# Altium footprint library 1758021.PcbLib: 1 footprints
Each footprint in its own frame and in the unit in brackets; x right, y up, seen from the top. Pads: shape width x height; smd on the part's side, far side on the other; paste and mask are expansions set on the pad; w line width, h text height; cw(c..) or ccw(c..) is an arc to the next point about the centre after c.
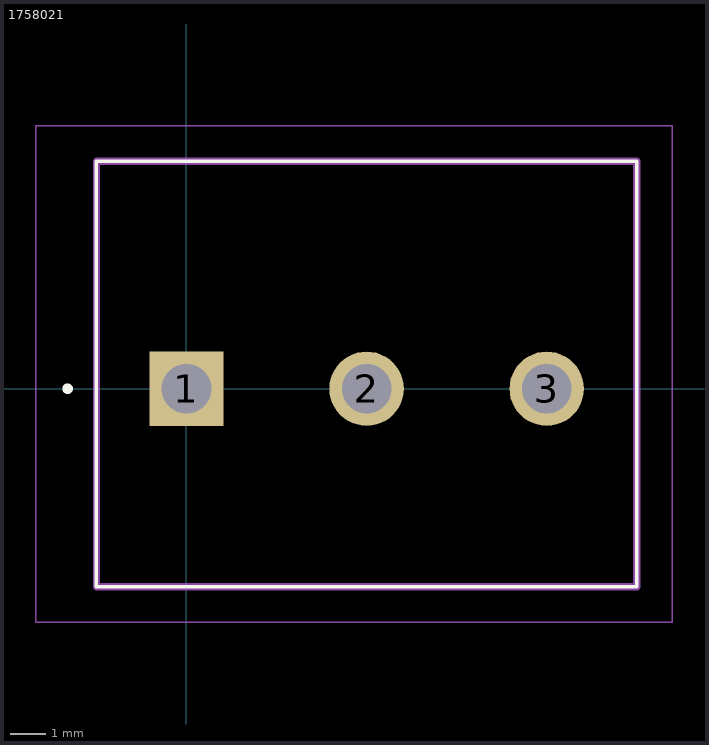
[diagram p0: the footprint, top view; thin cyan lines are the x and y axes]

## 1758021 [mm]
pads (3):
  rect 2.1x2.1 / inner round 2.1 / far side rect 2.1x2.1 hole 1.4: 1(0,0)
  round 2.1 hole 1.4: 2(5.08,0) 3(10.16,0)
Top Overlay:
  circle w0.2: c-3.35,0 r0.05
  lines w0.1: -2.54,-5.585 -2.54,6.415 12.7,6.415 12.7,-5.585 -2.54,-5.585
Mechanical 15:
  lines w0.2: -2.54,-5.585 -2.54,6.415 12.7,6.415 12.7,-5.585 -2.54,-5.585
Mechanical 20:
  lines w0.05: -4.25,-6.585 -4.25,7.415 13.7,7.415 13.7,-6.585 -4.25,-6.585
3D body "1758021.stp": height 5.8, standoff -4.65, extent -10,-3.376 10,3.376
